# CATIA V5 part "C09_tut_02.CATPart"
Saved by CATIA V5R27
Part number: Part1
Bounding box of the stored display mesh (mm): x -258 to 0, y -74.587 to 74.587, z -81.796 to 81.796
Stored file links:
  E:\_Deepak\2017_Deepak\CATIA\Resources\Tutorial Files\Tutorials\c09_catia_v5_6r2016_tut\C09_tut_02.CATPart
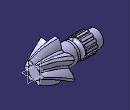
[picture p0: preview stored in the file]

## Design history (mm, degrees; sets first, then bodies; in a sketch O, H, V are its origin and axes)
Body1 (main body)
  Sketch1 on zx-plane, origin (0, 0, 0), H (-1, 0, 0), V (0, 0, 1)
    line L1 (0, 0) -> (258, 0)
    line L2 (258, 0) -> (258, -32.5)
    line L3 (0, 0) -> (0, -25)
    line L4 (0, -25) -> (95, -50)
    point P4 (95, -50)
    point P5 (95, -50)
    line L5 (95, -50) -> (95, -45)
    line L6 (95, -45) -> (100, -45)
    line L7 (100, -45) -> (100, -39)
    line L8 (100, -39) -> (146, -39)
    line L9 (258, -32.5) -> (226, -32.5)
    line L10 (226, -32.5) -> (226, -36)
    line L11 (226, -36) -> (178, -36)
    arc A1 centre (167, -36) radius 11 from (178, -36) to (156, -36) ccw
    point P13 (167, -36)
    line L12 (146, -39) -> (146, -38)
    line L13 (146, -38) -> (156, -38)
    line L14 (156, -38) -> (156, -36)
    point P16 (156, -36)
    point P17 (156, -36)
    axis line L15 (258, 0) -> (-34.5416, 0)
    length L1 = 258
    length L2 = 32.5
    length L3 = 25
    distance P4 L3 = 95
    length L6 = 5
    distance L6 L1 = 45
    length L9 = 32
    radius A1 = 11
    length L13 = 10
    length L14 = 2
    distance L13 L1 = 38
    length L11 = 48
    distance L8 L1 = 39
    distance P4 L1 = 50
    distance L11 L1 = 36
    horizontal: L1 H, L6 H, L8 H, L9 H, L11 H, L13 H, L15 H
    vertical: L2 V, L3 V, L5 V, L7 V, L10 V, L12 V, L14 V
    coincidence: P5 P4, P13 L11, P16 P17
  Shaft1: profile Sketch1, axis Sketch1.L15, angle 360
  Sketch2 on face of Shaft1 from Sketch1.L10, origin (-226, 0, 0), H (0, -1, 0), V (0, 0, 1)
    line L1 (-5, 40.6511) -> (5, 40.6511)
    line L2 (5, 40.6511) -> (5, 35.6511)
    line L3 (-5, 35.6511) -> (-5, 40.6511)
    point P3 (5, 35.6511)
    point P4 (-5, 35.6511)
    reference projected circle E1 centre (0, 0) radius 36 from edge [face of Shaft1 from Sketch1.L10 | face of Shaft1 from Sketch1.L11]
    reference projected circle E2 centre (0, 0) radius 36 from edge [face of Shaft1 from Sketch1.L10 | face of Shaft1 from Sketch1.L11]
    point P5 (0, 35.9986)
    point P6 (12.0414, 33.9264)
    arc A1 centre (0, 0) radius 36 from (5, 35.6511) to (-5, 35.6511) ccw
    length L3 = 5
    length L1 = 10
    distance L2 V = 5
    horizontal: L1 H
    vertical: L2 V, L3 V
    coincidence: P3 E1, P4 E2, P5 V
  Pad1: profile Sketch2, direction (1, 0, 0), length 48
  CircPattern1: of Pad1, instances 13, angular step 27.6923 {= 360.0*1 deg/CircPattern1.AngularNumber}, axis from face of Shaft1 from Sketch1.L9
  Plane1: type Offset, RefPlane face of Shaft1 from Sketch1.L2, Offset 163
  Sketch3 on Plane1, origin (-95, 0, 0), H (0, 1, 0), V (0, 0, 1)
    projected circle E1 centre (0, 0) radius 50 from edge [face of Shaft1 from Sketch1.L5 | face of Shaft1 from Sketch1.L4]
    projected arc E2 centre (0, 0) radius 50 from (20, 45.8258) to (-20, 45.8258) ccw from edge [face of Shaft1 from Sketch1.L5 | face of Shaft1 from Sketch1.L4]
    arc A1 centre (44.9551, 43.4104) radius 65 from (-20, 45.8258) to (-7.5, 81.7961) cw
    point P2 (-20, 45.8258)
    point P3 (-7.5, 81.7961)
    point P4 (20, 45.8258)
    point P5 (7.5, 81.7961)
    arc A2 centre (-44.9551, 43.4104) radius 65 from (20, 45.8258) to (7.5, 81.7961) ccw
    line L1 (-7.5, 81.7961) -> (7.5, 81.7961)
    radius A1 = 65
    length L1 = 15
    distance P2 P4 = 40
    coincidence: P2 E1
    symmetry: P2 P4 V, P3 P5 V, A1 A2 V
    horizontal: L1 H
  Plane2: type Offset, RefPlane face of Shaft1 from Sketch1.L2, Offset 210
  Sketch4 on Plane2, origin (-48, 0, 0), H (0, 1, 0), V (0, 0, 1)
    arc A1 centre (0, 0) radius 37.5 from (5.5935, 37.0805) to (-23.3843, 29.3159) ccw
    point P1 (5.5935, 37.0805)
    point P2 (-23.3843, 29.3159)
    arc A2 centre (-40.9945, 22.7216) radius 48.7506 from (5.5935, 37.0805) to (-10.4445, 60.7126) ccw
    point P3 (-10.4445, 60.7126)
    line L1 (-10.4445, 60.7126) -> (-21.3111, 57.8008)
    point P4 (-21.3111, 57.8008)
    arc A3 centre (24.1415, 40.1748) radius 48.7506 from (-21.3111, 57.8008) to (-23.3843, 29.3159) ccw
    reference projected circle E1 centre (0, 0) radius 25 from edge [face of Shaft1 from Sketch1.L4 | face of Shaft1 from Sketch1.L3]
    length L1 = 11.25
    radius A3 = 48.7506
    radius A1 = 37.5
    angle L1 H = 15
    radius A2 = 48.7506
    distance P1 V = 5.5935
    distance P2 V = 23.3843
    distance P3 V = 10.4445
    distance P4 H = 57.8008
    concentricity: A1 E1
  Sketch5 on face of Shaft1 from Sketch1.L3, origin (0, 0, 0), H (0, 1, 0), V (0, 0, 1)
    arc A1 centre (0, 0) radius 25 from (-2.7962, 24.8431) to (-20.1167, 14.8431) ccw
    arc A2 centre (-30.319, 7.5582) radius 32.5004 from (-2.7962, 24.8431) to (-17.2014, 37.2937) ccw
    line L1 (-17.2014, 37.2937) -> (-23.6966, 33.5437)
    arc A3 centre (8.6139, 30.0361) radius 32.5004 from (-23.6966, 33.5437) to (-20.1167, 14.8431) ccw
  Loft1: solid, Sections (Sketch3; Sketch4; Sketch5)
  CircPattern2: of Loft1, instances 6, angular step 60 {= 360.0*1 deg/CircPattern2.AngularNumber}, axis from face of Shaft1 from Sketch1.L4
